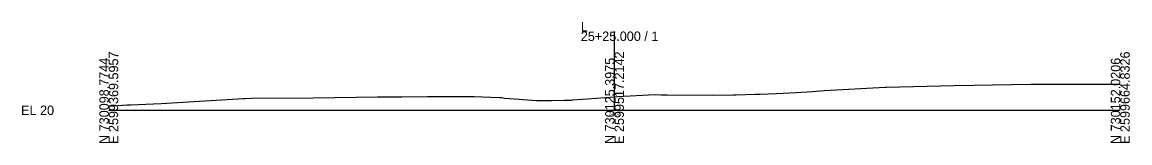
# Model space of a CAD drawing. Extents: x -26 to 3303, y -10 to 9555.
# Drawn here: x 2974.3 to 3302.8, y 490.3 to 526.2 of the extents above; entities that cross this region are included whole.
import ezdxf

# ---------------------------------------------------------------- set-up
doc = ezdxf.new("R2010")
doc.units = 0
for name, color, linetype in [('Exist Cross Section Cell', 7, 'Continuous'), ('Exist XS Center Line Elevation Label', 7, 'Continuous'), ('Exist XS Ground Line', 7, 'Continuous')]:
    doc.layers.add(name, color=color, linetype=linetype)

msp = doc.modelspace()

# ---------------------------------------------------------------- linework, layer by layer
at = {"layer": 'Exist Cross Section Cell'}
for p, q in [((3150, 500), (3150, 523.42)), ((3000, 500), (3150, 500)), ((3150, 500), (3300, 500))]:
    msp.add_line(p, q, dxfattribs=at)
at = {"layer": 'Exist XS Ground Line'}
msp.add_lwpolyline([(3000, 501.26), (3005.46, 501.59), (3006.45, 501.65), (3015.5, 502.06), (3039.94, 503.49), (3040.43, 503.52), (3042.37, 503.59), (3060.64, 503.71), (3079.74, 503.97), (3081.72, 503.96), (3083.81, 504), (3086.92, 503.99), (3094.52, 504.07), (3108.34, 504.14), (3115.74, 503.85), (3116.54, 503.77), (3117.33, 503.62), (3121.68, 503.27), (3122.81, 503.22), (3126.82, 502.93), (3129.92, 502.94), (3131.27, 502.89), (3135.15, 503), (3137.22, 503.01), (3137.53, 503.07), (3141.96, 503.4), (3150, 504.02), (3150.98, 504.1), (3158.33, 504.49), (3161.88, 504.68), (3163.85, 504.64), (3165.58, 504.62), (3179.01, 504.47), (3185.32, 504.58), (3186.06, 504.58), (3191.72, 504.77), (3193.19, 504.83), (3197.95, 504.99), (3202.03, 505.16), (3203.84, 505.26), (3208.76, 505.61), (3212.17, 505.88), (3230.31, 506.9), (3230.71, 506.91), (3250.59, 507.39), (3256.69, 507.42), (3262.07, 507.59), (3273.62, 507.78), (3277.43, 507.81), (3278.5, 507.81), (3280.87, 507.81), (3286.51, 507.78), (3290.42, 507.75), (3300, 507.78)], dxfattribs=at)

# ---------------------------------------------------------------- texts
at = {"layer": 'Exist Cross Section Cell'}
for s, p in [('L', (3140, 523.42)), ('25+25.000 / 1', (3140, 520.62)), ('EL 20', (2974, 498.6))]:
    msp.add_text(s, height=2.8, dxfattribs=at).set_placement(p)
for s, p in [('E 2599369.5957', (3002.8, 490)), ('E 2599517.2142', (3152.8, 490)), ('E 2599664.8326', (3302.8, 490)), ('N 730098.7744', (3000, 490)), ('N 730125.3975', (3150, 490)), ('N 730152.0206', (3300, 490))]:
    msp.add_text(s, height=2.8, rotation=90, dxfattribs=at).set_placement(p)
at = {"layer": 'Exist XS Center Line Elevation Label'}
msp.add_text('24.02', height=1, dxfattribs=at).set_placement((3148.29, 498.52))

doc.saveas('drawing.dxf')
